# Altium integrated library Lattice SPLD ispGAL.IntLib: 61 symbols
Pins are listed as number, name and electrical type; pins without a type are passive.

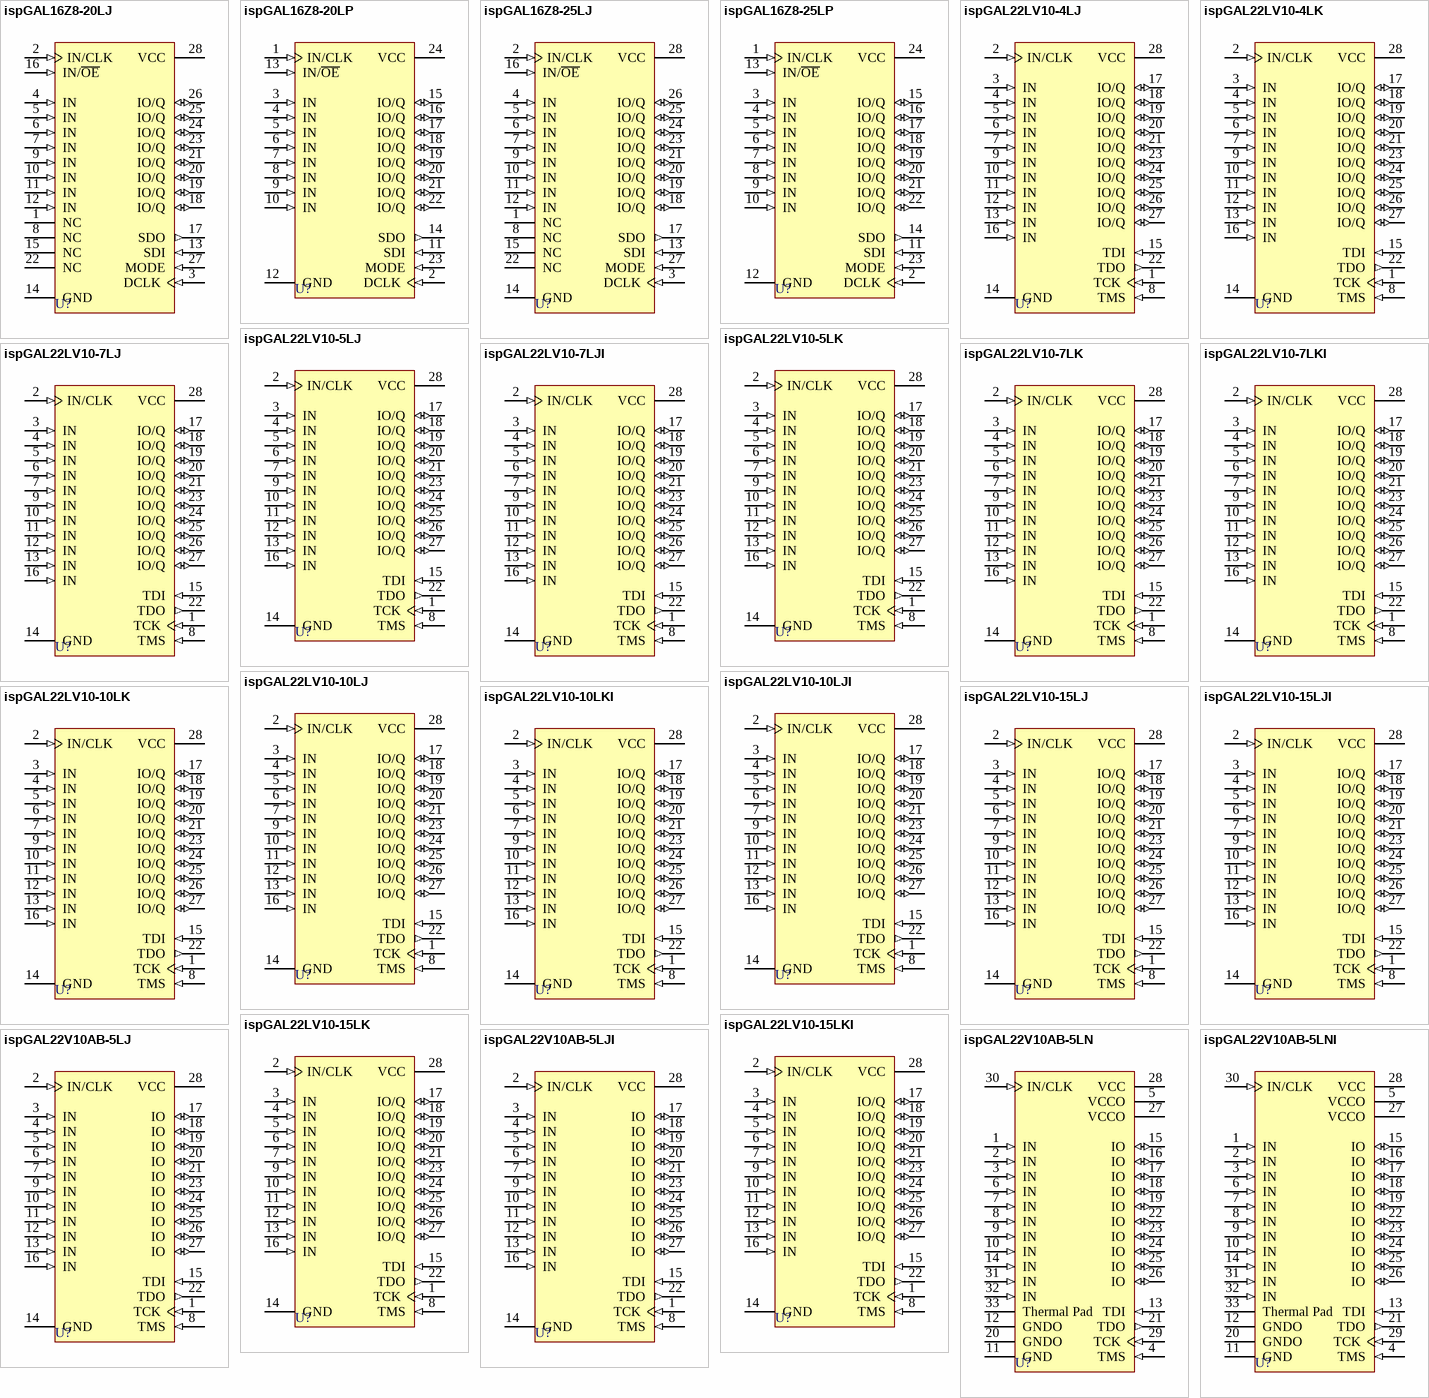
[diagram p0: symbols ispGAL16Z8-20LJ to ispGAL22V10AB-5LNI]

## ispGAL16Z8-20LJ
designator U?
ispGAL16Z8 E²CMOS PLD Generic Array Logic: Low Power, 5.0 V, 20 ns, Commercial Grade; Note: Pins 1, 8, 15 and 22 are No internal Connection (NC) pins.
footprint PLCC28_N (Leaded Chip Carrier, 28-Leads, Body 11.5x11.5mm, Pitch 1.27mm, IPC Medium Density)
footprint PLCC28_L (Leaded Chip Carrier, 28-Leads, Body 11.5x11.5mm, Pitch 1.27mm, IPC High Density)
footprint PLCC28_M (Leaded Chip Carrier, 28-Leads, Body 11.5x11.5mm, Pitch 1.27mm, IPC Low Density)
3D model 16Z8-PLCC28 (28-Pin Leaded Chip Carrier 1.27 mm Pitch)
pins: 1 NC, 2 IN/CLK (in), 3 DCLK (in), 4 IN (in), 5 IN (in), 6 IN (in), 7 IN (in), 8 NC, 9 IN (in), 10 IN (in), 11 IN (in), 12 IN (in), 13 SDI (in), 14 GND (power), 15 NC, 16 IN/~{OE} (in), 17 SDO (out), 18 IO/Q (io), 19 IO/Q (io), 20 IO/Q (io), 21 IO/Q (io), 22 NC, 23 IO/Q (io), 24 IO/Q (io), 25 IO/Q (io), 26 IO/Q (io), 27 MODE (in), 28 VCC (power)

## ispGAL16Z8-20LP
designator U?
ispGAL16Z8 E²CMOS PLD Generic Array Logic: Low Power, 5.0 V, 20 ns, Commercial Grade
footprint PDIP24 (DIP; 24 Leads; Row Spacing 7.62 mm; Pitch 2.54 mm)
3D model DIP24 (DIP; 24 Leads; Row Spacing 7.62 mm; Pitch 2.54 mm)
pins: 1 IN/CLK (in), 2 DCLK (in), 3 IN (in), 4 IN (in), 5 IN (in), 6 IN (in), 7 IN (in), 8 IN (in), 9 IN (in), 10 IN (in), 11 SDI (in), 12 GND (power), 13 IN/~{OE} (in), 14 SDO (out), 15 IO/Q (io), 16 IO/Q (io), 17 IO/Q (io), 18 IO/Q (io), 19 IO/Q (io), 20 IO/Q (io), 21 IO/Q (io), 22 IO/Q (io), 23 MODE (in), 24 VCC (power)

## ispGAL16Z8-25LJ
designator U?
ispGAL16Z8 E²CMOS PLD Generic Array Logic: Low Power, 5.0 V, 25 ns, Commercial Grade; Note: Pins 1, 8, 15 and 22 are No internal Connection (NC) pins.
footprint PLCC28_N (Leaded Chip Carrier, 28-Leads, Body 11.5x11.5mm, Pitch 1.27mm, IPC Medium Density)
footprint PLCC28_L (Leaded Chip Carrier, 28-Leads, Body 11.5x11.5mm, Pitch 1.27mm, IPC High Density)
footprint PLCC28_M (Leaded Chip Carrier, 28-Leads, Body 11.5x11.5mm, Pitch 1.27mm, IPC Low Density)
3D model 16Z8-PLCC28 (28-Pin Leaded Chip Carrier 1.27 mm Pitch)
pins: 1 NC, 2 IN/CLK (in), 3 DCLK (in), 4 IN (in), 5 IN (in), 6 IN (in), 7 IN (in), 8 NC, 9 IN (in), 10 IN (in), 11 IN (in), 12 IN (in), 13 SDI (in), 14 GND (power), 15 NC, 16 IN/~{OE} (in), 17 SDO (out), 18 IO/Q (io), 19 IO/Q (io), 20 IO/Q (io), 21 IO/Q (io), 22 NC, 23 IO/Q (io), 24 IO/Q (io), 25 IO/Q (io), 26 IO/Q (io), 27 MODE (in), 28 VCC (power)

## ispGAL16Z8-25LP
designator U?
ispGAL16Z8 E²CMOS PLD Generic Array Logic: Low Power, 5.0 V, 25 ns, Commercial Grade
footprint PDIP24 (DIP; 24 Leads; Row Spacing 7.62 mm; Pitch 2.54 mm)
3D model DIP24 (DIP; 24 Leads; Row Spacing 7.62 mm; Pitch 2.54 mm)
pins: 1 IN/CLK (in), 2 DCLK (in), 3 IN (in), 4 IN (in), 5 IN (in), 6 IN (in), 7 IN (in), 8 IN (in), 9 IN (in), 10 IN (in), 11 SDI (in), 12 GND (power), 13 IN/~{OE} (in), 14 SDO (out), 15 IO/Q (io), 16 IO/Q (io), 17 IO/Q (io), 18 IO/Q (io), 19 IO/Q (io), 20 IO/Q (io), 21 IO/Q (io), 22 IO/Q (io), 23 MODE (in), 24 VCC (power)

## ispGAL22LV10-4LJ
designator U?
ispGAL22LV10 E²CMOS PLD Generic Array Logic: Low Power, 3.3 V, 4.0 ns, Commercial Grade
footprint PLCC28_N (Leaded Chip Carrier, 28-Leads, Body 11.5x11.5mm, Pitch 1.27mm, IPC Medium Density)
footprint PLCC28_L (Leaded Chip Carrier, 28-Leads, Body 11.5x11.5mm, Pitch 1.27mm, IPC High Density)
footprint PLCC28_M (Leaded Chip Carrier, 28-Leads, Body 11.5x11.5mm, Pitch 1.27mm, IPC Low Density)
3D model 22LV10-PLCC28 (28-Pin Leaded Chip Carrier 1.27 mm Pitch)
pins: 1 TCK (in), 2 IN/CLK (in), 3 IN (in), 4 IN (in), 5 IN (in), 6 IN (in), 7 IN (in), 8 TMS (in), 9 IN (in), 10 IN (in), 11 IN (in), 12 IN (in), 13 IN (in), 14 GND (power), 15 TDI (in), 16 IN (in), 17 IO/Q (io), 18 IO/Q (io), 19 IO/Q (io), 20 IO/Q (io), 21 IO/Q (io), 22 TDO (out), 23 IO/Q (io), 24 IO/Q (io), 25 IO/Q (io), 26 IO/Q (io), 27 IO/Q (io), 28 VCC (power)

## ispGAL22LV10-4LK
designator U?
ispGAL22LV10 E²CMOS PLD Generic Array Logic: Low Power, 3.3 V, 4.0 ns, Commercial Grade
footprint SSOP28 (SSOP; 28 Leads; Body Width 5.3 mm; Pitch 0.65 mm)
3D model SSOP28 (SSOP; 28 Leads; Body Width 5.3 mm; Pitch 0.65 mm)
pins: 1 TCK (in), 2 IN/CLK (in), 3 IN (in), 4 IN (in), 5 IN (in), 6 IN (in), 7 IN (in), 8 TMS (in), 9 IN (in), 10 IN (in), 11 IN (in), 12 IN (in), 13 IN (in), 14 GND (power), 15 TDI (in), 16 IN (in), 17 IO/Q (io), 18 IO/Q (io), 19 IO/Q (io), 20 IO/Q (io), 21 IO/Q (io), 22 TDO (out), 23 IO/Q (io), 24 IO/Q (io), 25 IO/Q (io), 26 IO/Q (io), 27 IO/Q (io), 28 VCC (power)

## ispGAL22LV10-5LJ
designator U?
ispGAL22LV10 E²CMOS PLD Generic Array Logic: Low Power, 3.3 V, 5.0 ns, Commercial Grade
footprint PLCC28_N (Leaded Chip Carrier, 28-Leads, Body 11.5x11.5mm, Pitch 1.27mm, IPC Medium Density)
footprint PLCC28_L (Leaded Chip Carrier, 28-Leads, Body 11.5x11.5mm, Pitch 1.27mm, IPC High Density)
footprint PLCC28_M (Leaded Chip Carrier, 28-Leads, Body 11.5x11.5mm, Pitch 1.27mm, IPC Low Density)
3D model 22LV10-PLCC28 (28-Pin Leaded Chip Carrier 1.27 mm Pitch)
pins: 1 TCK (in), 2 IN/CLK (in), 3 IN (in), 4 IN (in), 5 IN (in), 6 IN (in), 7 IN (in), 8 TMS (in), 9 IN (in), 10 IN (in), 11 IN (in), 12 IN (in), 13 IN (in), 14 GND (power), 15 TDI (in), 16 IN (in), 17 IO/Q (io), 18 IO/Q (io), 19 IO/Q (io), 20 IO/Q (io), 21 IO/Q (io), 22 TDO (out), 23 IO/Q (io), 24 IO/Q (io), 25 IO/Q (io), 26 IO/Q (io), 27 IO/Q (io), 28 VCC (power)

## ispGAL22LV10-5LK
designator U?
ispGAL22LV10 E²CMOS PLD Generic Array Logic: Low Power, 3.3 V, 5.0 ns, Commercial Grade
footprint SSOP28 (SSOP; 28 Leads; Body Width 5.3 mm; Pitch 0.65 mm)
3D model SSOP28 (SSOP; 28 Leads; Body Width 5.3 mm; Pitch 0.65 mm)
pins: 1 TCK (in), 2 IN/CLK (in), 3 IN (in), 4 IN (in), 5 IN (in), 6 IN (in), 7 IN (in), 8 TMS (in), 9 IN (in), 10 IN (in), 11 IN (in), 12 IN (in), 13 IN (in), 14 GND (power), 15 TDI (in), 16 IN (in), 17 IO/Q (io), 18 IO/Q (io), 19 IO/Q (io), 20 IO/Q (io), 21 IO/Q (io), 22 TDO (out), 23 IO/Q (io), 24 IO/Q (io), 25 IO/Q (io), 26 IO/Q (io), 27 IO/Q (io), 28 VCC (power)

## ispGAL22LV10-7LJ
designator U?
ispGAL22LV10 E²CMOS PLD Generic Array Logic: Low Power, 3.3 V, 7.5 ns, Commercial Grade
footprint PLCC28_N (Leaded Chip Carrier, 28-Leads, Body 11.5x11.5mm, Pitch 1.27mm, IPC Medium Density)
footprint PLCC28_L (Leaded Chip Carrier, 28-Leads, Body 11.5x11.5mm, Pitch 1.27mm, IPC High Density)
footprint PLCC28_M (Leaded Chip Carrier, 28-Leads, Body 11.5x11.5mm, Pitch 1.27mm, IPC Low Density)
3D model 22LV10-PLCC28 (28-Pin Leaded Chip Carrier 1.27 mm Pitch)
pins: 1 TCK (in), 2 IN/CLK (in), 3 IN (in), 4 IN (in), 5 IN (in), 6 IN (in), 7 IN (in), 8 TMS (in), 9 IN (in), 10 IN (in), 11 IN (in), 12 IN (in), 13 IN (in), 14 GND (power), 15 TDI (in), 16 IN (in), 17 IO/Q (io), 18 IO/Q (io), 19 IO/Q (io), 20 IO/Q (io), 21 IO/Q (io), 22 TDO (out), 23 IO/Q (io), 24 IO/Q (io), 25 IO/Q (io), 26 IO/Q (io), 27 IO/Q (io), 28 VCC (power)

## ispGAL22LV10-7LJI
designator U?
ispGAL22LV10 E²CMOS PLD Generic Array Logic: Low Power, 3.3 V, 7.5 ns, Industrial Grade
footprint PLCC28_N (Leaded Chip Carrier, 28-Leads, Body 11.5x11.5mm, Pitch 1.27mm, IPC Medium Density)
footprint PLCC28_L (Leaded Chip Carrier, 28-Leads, Body 11.5x11.5mm, Pitch 1.27mm, IPC High Density)
footprint PLCC28_M (Leaded Chip Carrier, 28-Leads, Body 11.5x11.5mm, Pitch 1.27mm, IPC Low Density)
3D model 22LV10-PLCC28 (28-Pin Leaded Chip Carrier 1.27 mm Pitch)
pins: 1 TCK (in), 2 IN/CLK (in), 3 IN (in), 4 IN (in), 5 IN (in), 6 IN (in), 7 IN (in), 8 TMS (in), 9 IN (in), 10 IN (in), 11 IN (in), 12 IN (in), 13 IN (in), 14 GND (power), 15 TDI (in), 16 IN (in), 17 IO/Q (io), 18 IO/Q (io), 19 IO/Q (io), 20 IO/Q (io), 21 IO/Q (io), 22 TDO (out), 23 IO/Q (io), 24 IO/Q (io), 25 IO/Q (io), 26 IO/Q (io), 27 IO/Q (io), 28 VCC (power)

## ispGAL22LV10-7LK
designator U?
ispGAL22LV10 E²CMOS PLD Generic Array Logic: Low Power, 3.3 V, 7.5 ns, Commercial Grade
footprint SSOP28 (SSOP; 28 Leads; Body Width 5.3 mm; Pitch 0.65 mm)
3D model SSOP28 (SSOP; 28 Leads; Body Width 5.3 mm; Pitch 0.65 mm)
pins: 1 TCK (in), 2 IN/CLK (in), 3 IN (in), 4 IN (in), 5 IN (in), 6 IN (in), 7 IN (in), 8 TMS (in), 9 IN (in), 10 IN (in), 11 IN (in), 12 IN (in), 13 IN (in), 14 GND (power), 15 TDI (in), 16 IN (in), 17 IO/Q (io), 18 IO/Q (io), 19 IO/Q (io), 20 IO/Q (io), 21 IO/Q (io), 22 TDO (out), 23 IO/Q (io), 24 IO/Q (io), 25 IO/Q (io), 26 IO/Q (io), 27 IO/Q (io), 28 VCC (power)

## ispGAL22LV10-7LKI
designator U?
ispGAL22LV10 E²CMOS PLD Generic Array Logic: Low Power, 3.3 V, 7.5 ns, Industrial Grade
footprint SSOP28 (SSOP; 28 Leads; Body Width 5.3 mm; Pitch 0.65 mm)
3D model SSOP28 (SSOP; 28 Leads; Body Width 5.3 mm; Pitch 0.65 mm)
pins: 1 TCK (in), 2 IN/CLK (in), 3 IN (in), 4 IN (in), 5 IN (in), 6 IN (in), 7 IN (in), 8 TMS (in), 9 IN (in), 10 IN (in), 11 IN (in), 12 IN (in), 13 IN (in), 14 GND (power), 15 TDI (in), 16 IN (in), 17 IO/Q (io), 18 IO/Q (io), 19 IO/Q (io), 20 IO/Q (io), 21 IO/Q (io), 22 TDO (out), 23 IO/Q (io), 24 IO/Q (io), 25 IO/Q (io), 26 IO/Q (io), 27 IO/Q (io), 28 VCC (power)

## ispGAL22LV10-10LJ
designator U?
ispGAL22LV10 E²CMOS PLD Generic Array Logic: Low Power, 3.3 V, 10 ns, Commercial Grade
footprint PLCC28_N (Leaded Chip Carrier, 28-Leads, Body 11.5x11.5mm, Pitch 1.27mm, IPC Medium Density)
footprint PLCC28_L (Leaded Chip Carrier, 28-Leads, Body 11.5x11.5mm, Pitch 1.27mm, IPC High Density)
footprint PLCC28_M (Leaded Chip Carrier, 28-Leads, Body 11.5x11.5mm, Pitch 1.27mm, IPC Low Density)
3D model 22LV10-PLCC28 (28-Pin Leaded Chip Carrier 1.27 mm Pitch)
pins: 1 TCK (in), 2 IN/CLK (in), 3 IN (in), 4 IN (in), 5 IN (in), 6 IN (in), 7 IN (in), 8 TMS (in), 9 IN (in), 10 IN (in), 11 IN (in), 12 IN (in), 13 IN (in), 14 GND (power), 15 TDI (in), 16 IN (in), 17 IO/Q (io), 18 IO/Q (io), 19 IO/Q (io), 20 IO/Q (io), 21 IO/Q (io), 22 TDO (out), 23 IO/Q (io), 24 IO/Q (io), 25 IO/Q (io), 26 IO/Q (io), 27 IO/Q (io), 28 VCC (power)

## ispGAL22LV10-10LJI
designator U?
ispGAL22LV10 E²CMOS PLD Generic Array Logic: Low Power, 3.3 V, 10 ns, Industrial Grade
footprint PLCC28_N (Leaded Chip Carrier, 28-Leads, Body 11.5x11.5mm, Pitch 1.27mm, IPC Medium Density)
footprint PLCC28_L (Leaded Chip Carrier, 28-Leads, Body 11.5x11.5mm, Pitch 1.27mm, IPC High Density)
footprint PLCC28_M (Leaded Chip Carrier, 28-Leads, Body 11.5x11.5mm, Pitch 1.27mm, IPC Low Density)
3D model 22LV10-PLCC28 (28-Pin Leaded Chip Carrier 1.27 mm Pitch)
pins: 1 TCK (in), 2 IN/CLK (in), 3 IN (in), 4 IN (in), 5 IN (in), 6 IN (in), 7 IN (in), 8 TMS (in), 9 IN (in), 10 IN (in), 11 IN (in), 12 IN (in), 13 IN (in), 14 GND (power), 15 TDI (in), 16 IN (in), 17 IO/Q (io), 18 IO/Q (io), 19 IO/Q (io), 20 IO/Q (io), 21 IO/Q (io), 22 TDO (out), 23 IO/Q (io), 24 IO/Q (io), 25 IO/Q (io), 26 IO/Q (io), 27 IO/Q (io), 28 VCC (power)

## ispGAL22LV10-10LK
designator U?
ispGAL22LV10 E²CMOS PLD Generic Array Logic: Low Power, 3.3 V, 10 ns, Commercial Grade
footprint SSOP28 (SSOP; 28 Leads; Body Width 5.3 mm; Pitch 0.65 mm)
3D model SSOP28 (SSOP; 28 Leads; Body Width 5.3 mm; Pitch 0.65 mm)
pins: 1 TCK (in), 2 IN/CLK (in), 3 IN (in), 4 IN (in), 5 IN (in), 6 IN (in), 7 IN (in), 8 TMS (in), 9 IN (in), 10 IN (in), 11 IN (in), 12 IN (in), 13 IN (in), 14 GND (power), 15 TDI (in), 16 IN (in), 17 IO/Q (io), 18 IO/Q (io), 19 IO/Q (io), 20 IO/Q (io), 21 IO/Q (io), 22 TDO (out), 23 IO/Q (io), 24 IO/Q (io), 25 IO/Q (io), 26 IO/Q (io), 27 IO/Q (io), 28 VCC (power)

## ispGAL22LV10-10LKI
designator U?
ispGAL22LV10 E²CMOS PLD Generic Array Logic: Low Power, 3.3 V, 10 ns, Industrial Grade
footprint SSOP28 (SSOP; 28 Leads; Body Width 5.3 mm; Pitch 0.65 mm)
3D model SSOP28 (SSOP; 28 Leads; Body Width 5.3 mm; Pitch 0.65 mm)
pins: 1 TCK (in), 2 IN/CLK (in), 3 IN (in), 4 IN (in), 5 IN (in), 6 IN (in), 7 IN (in), 8 TMS (in), 9 IN (in), 10 IN (in), 11 IN (in), 12 IN (in), 13 IN (in), 14 GND (power), 15 TDI (in), 16 IN (in), 17 IO/Q (io), 18 IO/Q (io), 19 IO/Q (io), 20 IO/Q (io), 21 IO/Q (io), 22 TDO (out), 23 IO/Q (io), 24 IO/Q (io), 25 IO/Q (io), 26 IO/Q (io), 27 IO/Q (io), 28 VCC (power)

## ispGAL22LV10-15LJ
designator U?
ispGAL22LV10 E²CMOS PLD Generic Array Logic: Low Power, 3.3 V, 15 ns, Commercial Grade
footprint PLCC28_N (Leaded Chip Carrier, 28-Leads, Body 11.5x11.5mm, Pitch 1.27mm, IPC Medium Density)
footprint PLCC28_L (Leaded Chip Carrier, 28-Leads, Body 11.5x11.5mm, Pitch 1.27mm, IPC High Density)
footprint PLCC28_M (Leaded Chip Carrier, 28-Leads, Body 11.5x11.5mm, Pitch 1.27mm, IPC Low Density)
3D model 22LV10-PLCC28 (28-Pin Leaded Chip Carrier 1.27 mm Pitch)
pins: 1 TCK (in), 2 IN/CLK (in), 3 IN (in), 4 IN (in), 5 IN (in), 6 IN (in), 7 IN (in), 8 TMS (in), 9 IN (in), 10 IN (in), 11 IN (in), 12 IN (in), 13 IN (in), 14 GND (power), 15 TDI (in), 16 IN (in), 17 IO/Q (io), 18 IO/Q (io), 19 IO/Q (io), 20 IO/Q (io), 21 IO/Q (io), 22 TDO (out), 23 IO/Q (io), 24 IO/Q (io), 25 IO/Q (io), 26 IO/Q (io), 27 IO/Q (io), 28 VCC (power)

## ispGAL22LV10-15LJI
designator U?
ispGAL22LV10 E²CMOS PLD Generic Array Logic: Low Power, 3.3 V, 15 ns, Industrial Grade
footprint PLCC28_N (Leaded Chip Carrier, 28-Leads, Body 11.5x11.5mm, Pitch 1.27mm, IPC Medium Density)
footprint PLCC28_L (Leaded Chip Carrier, 28-Leads, Body 11.5x11.5mm, Pitch 1.27mm, IPC High Density)
footprint PLCC28_M (Leaded Chip Carrier, 28-Leads, Body 11.5x11.5mm, Pitch 1.27mm, IPC Low Density)
3D model 22LV10-PLCC28 (28-Pin Leaded Chip Carrier 1.27 mm Pitch)
pins: 1 TCK (in), 2 IN/CLK (in), 3 IN (in), 4 IN (in), 5 IN (in), 6 IN (in), 7 IN (in), 8 TMS (in), 9 IN (in), 10 IN (in), 11 IN (in), 12 IN (in), 13 IN (in), 14 GND (power), 15 TDI (in), 16 IN (in), 17 IO/Q (io), 18 IO/Q (io), 19 IO/Q (io), 20 IO/Q (io), 21 IO/Q (io), 22 TDO (out), 23 IO/Q (io), 24 IO/Q (io), 25 IO/Q (io), 26 IO/Q (io), 27 IO/Q (io), 28 VCC (power)

## ispGAL22LV10-15LK
designator U?
ispGAL22LV10 E²CMOS PLD Generic Array Logic: Low Power, 3.3 V, 15 ns, Commercial Grade
footprint SSOP28 (SSOP; 28 Leads; Body Width 5.3 mm; Pitch 0.65 mm)
3D model SSOP28 (SSOP; 28 Leads; Body Width 5.3 mm; Pitch 0.65 mm)
pins: 1 TCK (in), 2 IN/CLK (in), 3 IN (in), 4 IN (in), 5 IN (in), 6 IN (in), 7 IN (in), 8 TMS (in), 9 IN (in), 10 IN (in), 11 IN (in), 12 IN (in), 13 IN (in), 14 GND (power), 15 TDI (in), 16 IN (in), 17 IO/Q (io), 18 IO/Q (io), 19 IO/Q (io), 20 IO/Q (io), 21 IO/Q (io), 22 TDO (out), 23 IO/Q (io), 24 IO/Q (io), 25 IO/Q (io), 26 IO/Q (io), 27 IO/Q (io), 28 VCC (power)

## ispGAL22LV10-15LKI
designator U?
ispGAL22LV10 E²CMOS PLD Generic Array Logic: Low Power, 3.3 V, 15 ns, Industrial Grade
footprint SSOP28 (SSOP; 28 Leads; Body Width 5.3 mm; Pitch 0.65 mm)
3D model SSOP28 (SSOP; 28 Leads; Body Width 5.3 mm; Pitch 0.65 mm)
pins: 1 TCK (in), 2 IN/CLK (in), 3 IN (in), 4 IN (in), 5 IN (in), 6 IN (in), 7 IN (in), 8 TMS (in), 9 IN (in), 10 IN (in), 11 IN (in), 12 IN (in), 13 IN (in), 14 GND (power), 15 TDI (in), 16 IN (in), 17 IO/Q (io), 18 IO/Q (io), 19 IO/Q (io), 20 IO/Q (io), 21 IO/Q (io), 22 TDO (out), 23 IO/Q (io), 24 IO/Q (io), 25 IO/Q (io), 26 IO/Q (io), 27 IO/Q (io), 28 VCC (power)

## ispGAL22V10AB-5LJ
designator U?
ispGAL22V10AB E²CMOS PLD Generic Array Logic: Low Power, 2.5 V, 5.0 ns, Commercial Grade
footprint PLCC28_N (Leaded Chip Carrier, 28-Leads, Body 11.5x11.5mm, Pitch 1.27mm, IPC Medium Density)
footprint PLCC28_L (Leaded Chip Carrier, 28-Leads, Body 11.5x11.5mm, Pitch 1.27mm, IPC High Density)
footprint PLCC28_M (Leaded Chip Carrier, 28-Leads, Body 11.5x11.5mm, Pitch 1.27mm, IPC Low Density)
3D model 22V10AB-PLCC28 (28-Pin Leaded Chip Carrier 1.27 mm Pitch)
pins: 1 TCK (in), 2 IN/CLK (in), 3 IN (in), 4 IN (in), 5 IN (in), 6 IN (in), 7 IN (in), 8 TMS (in), 9 IN (in), 10 IN (in), 11 IN (in), 12 IN (in), 13 IN (in), 14 GND (power), 15 TDI (in), 16 IN (in), 17 IO (io), 18 IO (io), 19 IO (io), 20 IO (io), 21 IO (io), 22 TDO (out), 23 IO (io), 24 IO (io), 25 IO (io), 26 IO (io), 27 IO (io), 28 VCC (power)

## ispGAL22V10AB-5LJI
designator U?
ispGAL22V10AB E²CMOS PLD Generic Array Logic: Low Power, 2.5 V, 5.0 ns, Industrial Grade
footprint PLCC28_N (Leaded Chip Carrier, 28-Leads, Body 11.5x11.5mm, Pitch 1.27mm, IPC Medium Density)
footprint PLCC28_L (Leaded Chip Carrier, 28-Leads, Body 11.5x11.5mm, Pitch 1.27mm, IPC High Density)
footprint PLCC28_M (Leaded Chip Carrier, 28-Leads, Body 11.5x11.5mm, Pitch 1.27mm, IPC Low Density)
3D model 22V10AB-PLCC28 (28-Pin Leaded Chip Carrier 1.27 mm Pitch)
pins: 1 TCK (in), 2 IN/CLK (in), 3 IN (in), 4 IN (in), 5 IN (in), 6 IN (in), 7 IN (in), 8 TMS (in), 9 IN (in), 10 IN (in), 11 IN (in), 12 IN (in), 13 IN (in), 14 GND (power), 15 TDI (in), 16 IN (in), 17 IO (io), 18 IO (io), 19 IO (io), 20 IO (io), 21 IO (io), 22 TDO (out), 23 IO (io), 24 IO (io), 25 IO (io), 26 IO (io), 27 IO (io), 28 VCC (power)

## ispGAL22V10AB-5LN
designator U?
ispGAL22V10AB E²CMOS PLD Generic Array Logic: Low Power, 2.5 V, 5.0 ns, Commercial Grade
footprint QFN32_N (QFN, 32-Leads, Body 5x5mm, Pitch 0.5mm, IPC Medium Density)
footprint QFN32_L (QFN, 32-Leads, Body 5x5mm, Pitch 0.5mm, IPC High Density)
footprint QFN32_M (QFN, 32-Leads, Body 5x5mm, Pitch 0.5mm, IPC Low Density)
pins: 1 IN (in), 2 IN (in), 3 IN (in), 4 TMS (in), 5 VCCO (power), 6 IN (in), 7 IN (in), 8 IN (in), 9 IN (in), 10 IN (in), 11 GND (power), 12 GNDO (power), 13 TDI (in), 14 IN (in), 15 IO (io), 16 IO (io), 17 IO (io), 18 IO (io), 19 IO (io), 20 GNDO (power), 21 TDO (out), 22 IO (io), 23 IO (io), 24 IO (io), 25 IO (io), 26 IO (io), 27 VCCO (power), 28 VCC (power), 29 TCK (in), 30 IN/CLK (in), 31 IN (in), 32 IN (in), 33 Thermal Pad (power)

## ispGAL22V10AB-5LNI
designator U?
ispGAL22V10AB E²CMOS PLD Generic Array Logic: Low Power, 2.5 V, 5.0 ns, Industrial Grade
footprint QFN32_N (QFN, 32-Leads, Body 5x5mm, Pitch 0.5mm, IPC Medium Density)
footprint QFN32_L (QFN, 32-Leads, Body 5x5mm, Pitch 0.5mm, IPC High Density)
footprint QFN32_M (QFN, 32-Leads, Body 5x5mm, Pitch 0.5mm, IPC Low Density)
pins: 1 IN (in), 2 IN (in), 3 IN (in), 4 TMS (in), 5 VCCO (power), 6 IN (in), 7 IN (in), 8 IN (in), 9 IN (in), 10 IN (in), 11 GND (power), 12 GNDO (power), 13 TDI (in), 14 IN (in), 15 IO (io), 16 IO (io), 17 IO (io), 18 IO (io), 19 IO (io), 20 GNDO (power), 21 TDO (out), 22 IO (io), 23 IO (io), 24 IO (io), 25 IO (io), 26 IO (io), 27 VCCO (power), 28 VCC (power), 29 TCK (in), 30 IN/CLK (in), 31 IN (in), 32 IN (in), 33 Thermal Pad (power)

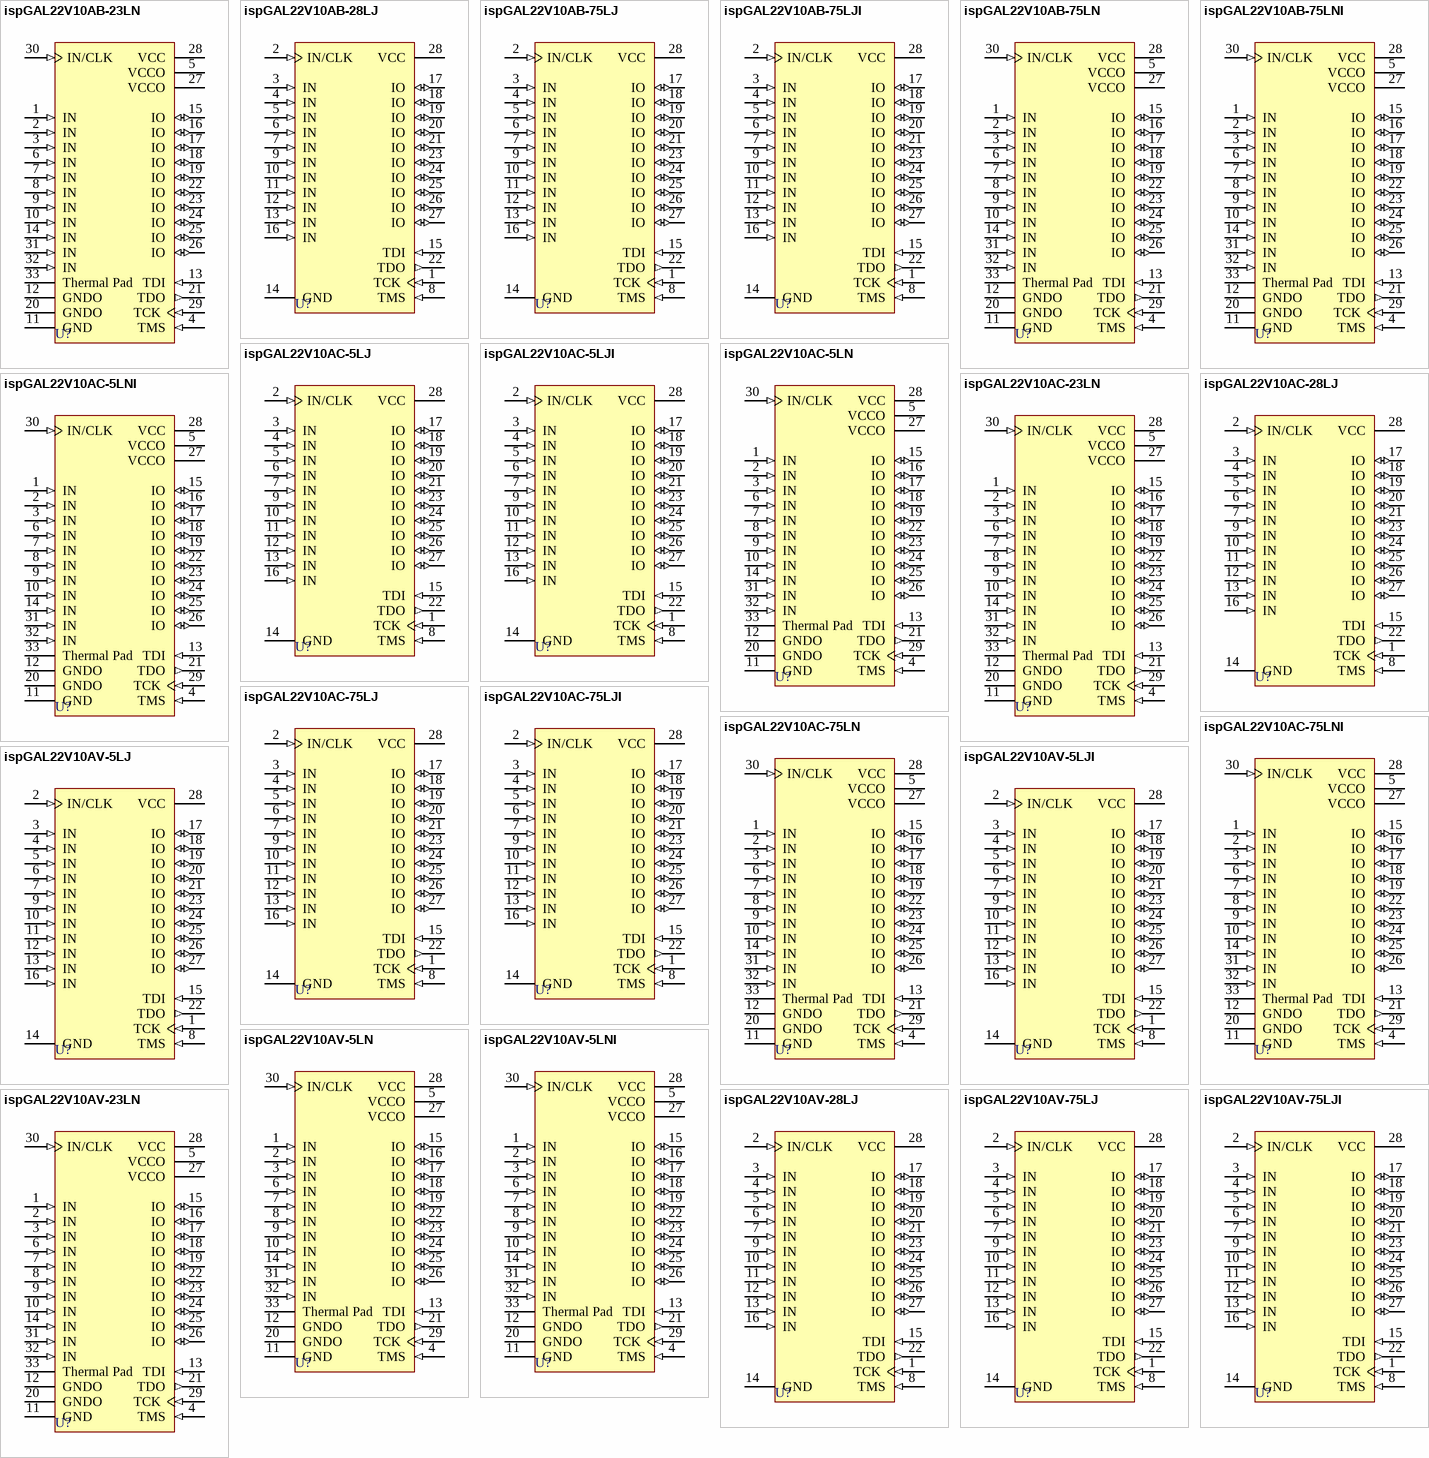
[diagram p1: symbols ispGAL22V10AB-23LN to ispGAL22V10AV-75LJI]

## ispGAL22V10AB-23LN
designator U?
ispGAL22V10AB E²CMOS PLD Generic Array Logic: Low Power, 2.5 V, 2.3 ns, Commercial Grade
footprint QFN32_N (QFN, 32-Leads, Body 5x5mm, Pitch 0.5mm, IPC Medium Density)
footprint QFN32_L (QFN, 32-Leads, Body 5x5mm, Pitch 0.5mm, IPC High Density)
footprint QFN32_M (QFN, 32-Leads, Body 5x5mm, Pitch 0.5mm, IPC Low Density)
pins: 1 IN (in), 2 IN (in), 3 IN (in), 4 TMS (in), 5 VCCO (power), 6 IN (in), 7 IN (in), 8 IN (in), 9 IN (in), 10 IN (in), 11 GND (power), 12 GNDO (power), 13 TDI (in), 14 IN (in), 15 IO (io), 16 IO (io), 17 IO (io), 18 IO (io), 19 IO (io), 20 GNDO (power), 21 TDO (out), 22 IO (io), 23 IO (io), 24 IO (io), 25 IO (io), 26 IO (io), 27 VCCO (power), 28 VCC (power), 29 TCK (in), 30 IN/CLK (in), 31 IN (in), 32 IN (in), 33 Thermal Pad (power)

## ispGAL22V10AB-28LJ
designator U?
ispGAL22V10AB E²CMOS PLD Generic Array Logic: Low Power, 2.5 V, 2.8 ns, Commercial Grade
footprint PLCC28_N (Leaded Chip Carrier, 28-Leads, Body 11.5x11.5mm, Pitch 1.27mm, IPC Medium Density)
footprint PLCC28_L (Leaded Chip Carrier, 28-Leads, Body 11.5x11.5mm, Pitch 1.27mm, IPC High Density)
footprint PLCC28_M (Leaded Chip Carrier, 28-Leads, Body 11.5x11.5mm, Pitch 1.27mm, IPC Low Density)
3D model 22V10AB-PLCC28 (28-Pin Leaded Chip Carrier 1.27 mm Pitch)
pins: 1 TCK (in), 2 IN/CLK (in), 3 IN (in), 4 IN (in), 5 IN (in), 6 IN (in), 7 IN (in), 8 TMS (in), 9 IN (in), 10 IN (in), 11 IN (in), 12 IN (in), 13 IN (in), 14 GND (power), 15 TDI (in), 16 IN (in), 17 IO (io), 18 IO (io), 19 IO (io), 20 IO (io), 21 IO (io), 22 TDO (out), 23 IO (io), 24 IO (io), 25 IO (io), 26 IO (io), 27 IO (io), 28 VCC (power)

## ispGAL22V10AB-75LJ
designator U?
ispGAL22V10AB E²CMOS PLD Generic Array Logic: Low Power, 2.5 V, 7.5 ns, Commercial Grade
footprint PLCC28_N (Leaded Chip Carrier, 28-Leads, Body 11.5x11.5mm, Pitch 1.27mm, IPC Medium Density)
footprint PLCC28_L (Leaded Chip Carrier, 28-Leads, Body 11.5x11.5mm, Pitch 1.27mm, IPC High Density)
footprint PLCC28_M (Leaded Chip Carrier, 28-Leads, Body 11.5x11.5mm, Pitch 1.27mm, IPC Low Density)
3D model 22V10AB-PLCC28 (28-Pin Leaded Chip Carrier 1.27 mm Pitch)
pins: 1 TCK (in), 2 IN/CLK (in), 3 IN (in), 4 IN (in), 5 IN (in), 6 IN (in), 7 IN (in), 8 TMS (in), 9 IN (in), 10 IN (in), 11 IN (in), 12 IN (in), 13 IN (in), 14 GND (power), 15 TDI (in), 16 IN (in), 17 IO (io), 18 IO (io), 19 IO (io), 20 IO (io), 21 IO (io), 22 TDO (out), 23 IO (io), 24 IO (io), 25 IO (io), 26 IO (io), 27 IO (io), 28 VCC (power)

## ispGAL22V10AB-75LJI
designator U?
ispGAL22V10AB E²CMOS PLD Generic Array Logic: Low Power, 2.5 V, 7.5 ns, Industrial Grade
footprint PLCC28_N (Leaded Chip Carrier, 28-Leads, Body 11.5x11.5mm, Pitch 1.27mm, IPC Medium Density)
footprint PLCC28_L (Leaded Chip Carrier, 28-Leads, Body 11.5x11.5mm, Pitch 1.27mm, IPC High Density)
footprint PLCC28_M (Leaded Chip Carrier, 28-Leads, Body 11.5x11.5mm, Pitch 1.27mm, IPC Low Density)
3D model 22V10AB-PLCC28 (28-Pin Leaded Chip Carrier 1.27 mm Pitch)
pins: 1 TCK (in), 2 IN/CLK (in), 3 IN (in), 4 IN (in), 5 IN (in), 6 IN (in), 7 IN (in), 8 TMS (in), 9 IN (in), 10 IN (in), 11 IN (in), 12 IN (in), 13 IN (in), 14 GND (power), 15 TDI (in), 16 IN (in), 17 IO (io), 18 IO (io), 19 IO (io), 20 IO (io), 21 IO (io), 22 TDO (out), 23 IO (io), 24 IO (io), 25 IO (io), 26 IO (io), 27 IO (io), 28 VCC (power)

## ispGAL22V10AB-75LN
designator U?
ispGAL22V10AB E²CMOS PLD Generic Array Logic: Low Power, 2.5 V, 7.5 ns, Commercial Grade
footprint QFN32_N (QFN, 32-Leads, Body 5x5mm, Pitch 0.5mm, IPC Medium Density)
footprint QFN32_L (QFN, 32-Leads, Body 5x5mm, Pitch 0.5mm, IPC High Density)
footprint QFN32_M (QFN, 32-Leads, Body 5x5mm, Pitch 0.5mm, IPC Low Density)
pins: 1 IN (in), 2 IN (in), 3 IN (in), 4 TMS (in), 5 VCCO (power), 6 IN (in), 7 IN (in), 8 IN (in), 9 IN (in), 10 IN (in), 11 GND (power), 12 GNDO (power), 13 TDI (in), 14 IN (in), 15 IO (io), 16 IO (io), 17 IO (io), 18 IO (io), 19 IO (io), 20 GNDO (power), 21 TDO (out), 22 IO (io), 23 IO (io), 24 IO (io), 25 IO (io), 26 IO (io), 27 VCCO (power), 28 VCC (power), 29 TCK (in), 30 IN/CLK (in), 31 IN (in), 32 IN (in), 33 Thermal Pad (power)

## ispGAL22V10AB-75LNI
designator U?
ispGAL22V10AB E²CMOS PLD Generic Array Logic: Low Power, 2.5 V, 7.5 ns, Industrial Grade
footprint QFN32_N (QFN, 32-Leads, Body 5x5mm, Pitch 0.5mm, IPC Medium Density)
footprint QFN32_L (QFN, 32-Leads, Body 5x5mm, Pitch 0.5mm, IPC High Density)
footprint QFN32_M (QFN, 32-Leads, Body 5x5mm, Pitch 0.5mm, IPC Low Density)
pins: 1 IN (in), 2 IN (in), 3 IN (in), 4 TMS (in), 5 VCCO (power), 6 IN (in), 7 IN (in), 8 IN (in), 9 IN (in), 10 IN (in), 11 GND (power), 12 GNDO (power), 13 TDI (in), 14 IN (in), 15 IO (io), 16 IO (io), 17 IO (io), 18 IO (io), 19 IO (io), 20 GNDO (power), 21 TDO (out), 22 IO (io), 23 IO (io), 24 IO (io), 25 IO (io), 26 IO (io), 27 VCCO (power), 28 VCC (power), 29 TCK (in), 30 IN/CLK (in), 31 IN (in), 32 IN (in), 33 Thermal Pad (power)

## ispGAL22V10AC-5LJ
designator U?
ispGAL22V10AC E²CMOS PLD Generic Array Logic: Low Power, 1.8 V, 5.0 ns, Commercial Grade
footprint PLCC28_N (Leaded Chip Carrier, 28-Leads, Body 11.5x11.5mm, Pitch 1.27mm, IPC Medium Density)
footprint PLCC28_L (Leaded Chip Carrier, 28-Leads, Body 11.5x11.5mm, Pitch 1.27mm, IPC High Density)
footprint PLCC28_M (Leaded Chip Carrier, 28-Leads, Body 11.5x11.5mm, Pitch 1.27mm, IPC Low Density)
3D model 22V10AC-PLCC28 (28-Pin Leaded Chip Carrier 1.27 mm Pitch)
pins: 1 TCK (in), 2 IN/CLK (in), 3 IN (in), 4 IN (in), 5 IN (in), 6 IN (in), 7 IN (in), 8 TMS (in), 9 IN (in), 10 IN (in), 11 IN (in), 12 IN (in), 13 IN (in), 14 GND (power), 15 TDI (in), 16 IN (in), 17 IO (io), 18 IO (io), 19 IO (io), 20 IO (io), 21 IO (io), 22 TDO (out), 23 IO (io), 24 IO (io), 25 IO (io), 26 IO (io), 27 IO (io), 28 VCC (power)

## ispGAL22V10AC-5LJI
designator U?
ispGAL22V10AC E²CMOS PLD Generic Array Logic: Low Power, 1.8 V, 5.0 ns, Industrial Grade
footprint PLCC28_N (Leaded Chip Carrier, 28-Leads, Body 11.5x11.5mm, Pitch 1.27mm, IPC Medium Density)
footprint PLCC28_L (Leaded Chip Carrier, 28-Leads, Body 11.5x11.5mm, Pitch 1.27mm, IPC High Density)
footprint PLCC28_M (Leaded Chip Carrier, 28-Leads, Body 11.5x11.5mm, Pitch 1.27mm, IPC Low Density)
3D model 22V10AC-PLCC28 (28-Pin Leaded Chip Carrier 1.27 mm Pitch)
pins: 1 TCK (in), 2 IN/CLK (in), 3 IN (in), 4 IN (in), 5 IN (in), 6 IN (in), 7 IN (in), 8 TMS (in), 9 IN (in), 10 IN (in), 11 IN (in), 12 IN (in), 13 IN (in), 14 GND (power), 15 TDI (in), 16 IN (in), 17 IO (io), 18 IO (io), 19 IO (io), 20 IO (io), 21 IO (io), 22 TDO (out), 23 IO (io), 24 IO (io), 25 IO (io), 26 IO (io), 27 IO (io), 28 VCC (power)

## ispGAL22V10AC-5LN
designator U?
ispGAL22V10AC E²CMOS PLD Generic Array Logic: Low Power, 1.8 V, 5.0 ns, Commercial Grade
footprint QFN32_N (QFN, 32-Leads, Body 5x5mm, Pitch 0.5mm, IPC Medium Density)
footprint QFN32_L (QFN, 32-Leads, Body 5x5mm, Pitch 0.5mm, IPC High Density)
footprint QFN32_M (QFN, 32-Leads, Body 5x5mm, Pitch 0.5mm, IPC Low Density)
pins: 1 IN (in), 2 IN (in), 3 IN (in), 4 TMS (in), 5 VCCO (power), 6 IN (in), 7 IN (in), 8 IN (in), 9 IN (in), 10 IN (in), 11 GND (power), 12 GNDO (power), 13 TDI (in), 14 IN (in), 15 IO (io), 16 IO (io), 17 IO (io), 18 IO (io), 19 IO (io), 20 GNDO (power), 21 TDO (out), 22 IO (io), 23 IO (io), 24 IO (io), 25 IO (io), 26 IO (io), 27 VCCO (power), 28 VCC (power), 29 TCK (in), 30 IN/CLK (in), 31 IN (in), 32 IN (in), 33 Thermal Pad (power)

## ispGAL22V10AC-5LNI
designator U?
ispGAL22V10AC E²CMOS PLD Generic Array Logic: Low Power, 1.8 V, 5.0 ns, Industrial Grade
footprint QFN32_N (QFN, 32-Leads, Body 5x5mm, Pitch 0.5mm, IPC Medium Density)
footprint QFN32_L (QFN, 32-Leads, Body 5x5mm, Pitch 0.5mm, IPC High Density)
footprint QFN32_M (QFN, 32-Leads, Body 5x5mm, Pitch 0.5mm, IPC Low Density)
pins: 1 IN (in), 2 IN (in), 3 IN (in), 4 TMS (in), 5 VCCO (power), 6 IN (in), 7 IN (in), 8 IN (in), 9 IN (in), 10 IN (in), 11 GND (power), 12 GNDO (power), 13 TDI (in), 14 IN (in), 15 IO (io), 16 IO (io), 17 IO (io), 18 IO (io), 19 IO (io), 20 GNDO (power), 21 TDO (out), 22 IO (io), 23 IO (io), 24 IO (io), 25 IO (io), 26 IO (io), 27 VCCO (power), 28 VCC (power), 29 TCK (in), 30 IN/CLK (in), 31 IN (in), 32 IN (in), 33 Thermal Pad (power)

## ispGAL22V10AC-23LN
designator U?
ispGAL22V10AC E²CMOS PLD Generic Array Logic: Low Power, 1.8 V, 2.3 ns, Commercial Grade
footprint QFN32_N (QFN, 32-Leads, Body 5x5mm, Pitch 0.5mm, IPC Medium Density)
footprint QFN32_L (QFN, 32-Leads, Body 5x5mm, Pitch 0.5mm, IPC High Density)
footprint QFN32_M (QFN, 32-Leads, Body 5x5mm, Pitch 0.5mm, IPC Low Density)
pins: 1 IN (in), 2 IN (in), 3 IN (in), 4 TMS (in), 5 VCCO (power), 6 IN (in), 7 IN (in), 8 IN (in), 9 IN (in), 10 IN (in), 11 GND (power), 12 GNDO (power), 13 TDI (in), 14 IN (in), 15 IO (io), 16 IO (io), 17 IO (io), 18 IO (io), 19 IO (io), 20 GNDO (power), 21 TDO (out), 22 IO (io), 23 IO (io), 24 IO (io), 25 IO (io), 26 IO (io), 27 VCCO (power), 28 VCC (power), 29 TCK (in), 30 IN/CLK (in), 31 IN (in), 32 IN (in), 33 Thermal Pad (power)

## ispGAL22V10AC-28LJ
designator U?
ispGAL22V10AC E²CMOS PLD Generic Array Logic: Low Power, 1.8 V, 2.8 ns, Commercial Grade
footprint PLCC28_N (Leaded Chip Carrier, 28-Leads, Body 11.5x11.5mm, Pitch 1.27mm, IPC Medium Density)
footprint PLCC28_L (Leaded Chip Carrier, 28-Leads, Body 11.5x11.5mm, Pitch 1.27mm, IPC High Density)
footprint PLCC28_M (Leaded Chip Carrier, 28-Leads, Body 11.5x11.5mm, Pitch 1.27mm, IPC Low Density)
3D model 22V10AC-PLCC28 (28-Pin Leaded Chip Carrier 1.27 mm Pitch)
pins: 1 TCK (in), 2 IN/CLK (in), 3 IN (in), 4 IN (in), 5 IN (in), 6 IN (in), 7 IN (in), 8 TMS (in), 9 IN (in), 10 IN (in), 11 IN (in), 12 IN (in), 13 IN (in), 14 GND (power), 15 TDI (in), 16 IN (in), 17 IO (io), 18 IO (io), 19 IO (io), 20 IO (io), 21 IO (io), 22 TDO (out), 23 IO (io), 24 IO (io), 25 IO (io), 26 IO (io), 27 IO (io), 28 VCC (power)

## ispGAL22V10AC-75LJ
designator U?
ispGAL22V10AC E²CMOS PLD Generic Array Logic: Low Power, 1.8 V, 7.5 ns, Commercial Grade
footprint PLCC28_N (Leaded Chip Carrier, 28-Leads, Body 11.5x11.5mm, Pitch 1.27mm, IPC Medium Density)
footprint PLCC28_L (Leaded Chip Carrier, 28-Leads, Body 11.5x11.5mm, Pitch 1.27mm, IPC High Density)
footprint PLCC28_M (Leaded Chip Carrier, 28-Leads, Body 11.5x11.5mm, Pitch 1.27mm, IPC Low Density)
3D model 22V10AC-PLCC28 (28-Pin Leaded Chip Carrier 1.27 mm Pitch)
pins: 1 TCK (in), 2 IN/CLK (in), 3 IN (in), 4 IN (in), 5 IN (in), 6 IN (in), 7 IN (in), 8 TMS (in), 9 IN (in), 10 IN (in), 11 IN (in), 12 IN (in), 13 IN (in), 14 GND (power), 15 TDI (in), 16 IN (in), 17 IO (io), 18 IO (io), 19 IO (io), 20 IO (io), 21 IO (io), 22 TDO (out), 23 IO (io), 24 IO (io), 25 IO (io), 26 IO (io), 27 IO (io), 28 VCC (power)

## ispGAL22V10AC-75LJI
designator U?
ispGAL22V10AC E²CMOS PLD Generic Array Logic: Low Power, 1.8 V, 7.5 ns, Industrial Grade
footprint PLCC28_N (Leaded Chip Carrier, 28-Leads, Body 11.5x11.5mm, Pitch 1.27mm, IPC Medium Density)
footprint PLCC28_L (Leaded Chip Carrier, 28-Leads, Body 11.5x11.5mm, Pitch 1.27mm, IPC High Density)
footprint PLCC28_M (Leaded Chip Carrier, 28-Leads, Body 11.5x11.5mm, Pitch 1.27mm, IPC Low Density)
3D model 22V10AC-PLCC28 (28-Pin Leaded Chip Carrier 1.27 mm Pitch)
pins: 1 TCK (in), 2 IN/CLK (in), 3 IN (in), 4 IN (in), 5 IN (in), 6 IN (in), 7 IN (in), 8 TMS (in), 9 IN (in), 10 IN (in), 11 IN (in), 12 IN (in), 13 IN (in), 14 GND (power), 15 TDI (in), 16 IN (in), 17 IO (io), 18 IO (io), 19 IO (io), 20 IO (io), 21 IO (io), 22 TDO (out), 23 IO (io), 24 IO (io), 25 IO (io), 26 IO (io), 27 IO (io), 28 VCC (power)

## ispGAL22V10AC-75LN
designator U?
ispGAL22V10AC E²CMOS PLD Generic Array Logic: Low Power, 1.8 V, 7.5 ns, Commercial Grade
footprint QFN32_N (QFN, 32-Leads, Body 5x5mm, Pitch 0.5mm, IPC Medium Density)
footprint QFN32_L (QFN, 32-Leads, Body 5x5mm, Pitch 0.5mm, IPC High Density)
footprint QFN32_M (QFN, 32-Leads, Body 5x5mm, Pitch 0.5mm, IPC Low Density)
pins: 1 IN (in), 2 IN (in), 3 IN (in), 4 TMS (in), 5 VCCO (power), 6 IN (in), 7 IN (in), 8 IN (in), 9 IN (in), 10 IN (in), 11 GND (power), 12 GNDO (power), 13 TDI (in), 14 IN (in), 15 IO (io), 16 IO (io), 17 IO (io), 18 IO (io), 19 IO (io), 20 GNDO (power), 21 TDO (out), 22 IO (io), 23 IO (io), 24 IO (io), 25 IO (io), 26 IO (io), 27 VCCO (power), 28 VCC (power), 29 TCK (in), 30 IN/CLK (in), 31 IN (in), 32 IN (in), 33 Thermal Pad (power)

## ispGAL22V10AC-75LNI
designator U?
ispGAL22V10AC E²CMOS PLD Generic Array Logic: Low Power, 1.8 V, 7.5 ns, Industrial Grade
footprint QFN32_N (QFN, 32-Leads, Body 5x5mm, Pitch 0.5mm, IPC Medium Density)
footprint QFN32_L (QFN, 32-Leads, Body 5x5mm, Pitch 0.5mm, IPC High Density)
footprint QFN32_M (QFN, 32-Leads, Body 5x5mm, Pitch 0.5mm, IPC Low Density)
pins: 1 IN (in), 2 IN (in), 3 IN (in), 4 TMS (in), 5 VCCO (power), 6 IN (in), 7 IN (in), 8 IN (in), 9 IN (in), 10 IN (in), 11 GND (power), 12 GNDO (power), 13 TDI (in), 14 IN (in), 15 IO (io), 16 IO (io), 17 IO (io), 18 IO (io), 19 IO (io), 20 GNDO (power), 21 TDO (out), 22 IO (io), 23 IO (io), 24 IO (io), 25 IO (io), 26 IO (io), 27 VCCO (power), 28 VCC (power), 29 TCK (in), 30 IN/CLK (in), 31 IN (in), 32 IN (in), 33 Thermal Pad (power)

## ispGAL22V10AV-5LJ
designator U?
ispGAL22V10AV E²CMOS PLD Generic Array Logic: Low Power, 3.3 V, 5.0 ns, Commercial Grade
footprint PLCC28_N (Leaded Chip Carrier, 28-Leads, Body 11.5x11.5mm, Pitch 1.27mm, IPC Medium Density)
footprint PLCC28_L (Leaded Chip Carrier, 28-Leads, Body 11.5x11.5mm, Pitch 1.27mm, IPC High Density)
footprint PLCC28_M (Leaded Chip Carrier, 28-Leads, Body 11.5x11.5mm, Pitch 1.27mm, IPC Low Density)
3D model 22V10AV-PLCC28 (28-Pin Leaded Chip Carrier 1.27 mm Pitch)
pins: 1 TCK (in), 2 IN/CLK (in), 3 IN (in), 4 IN (in), 5 IN (in), 6 IN (in), 7 IN (in), 8 TMS (in), 9 IN (in), 10 IN (in), 11 IN (in), 12 IN (in), 13 IN (in), 14 GND (power), 15 TDI (in), 16 IN (in), 17 IO (io), 18 IO (io), 19 IO (io), 20 IO (io), 21 IO (io), 22 TDO (out), 23 IO (io), 24 IO (io), 25 IO (io), 26 IO (io), 27 IO (io), 28 VCC (power)

## ispGAL22V10AV-5LJI
designator U?
ispGAL22V10AV E²CMOS PLD Generic Array Logic: Low Power, 3.3 V, 5.0 ns, Industrial Grade
footprint PLCC28_N (Leaded Chip Carrier, 28-Leads, Body 11.5x11.5mm, Pitch 1.27mm, IPC Medium Density)
footprint PLCC28_L (Leaded Chip Carrier, 28-Leads, Body 11.5x11.5mm, Pitch 1.27mm, IPC High Density)
footprint PLCC28_M (Leaded Chip Carrier, 28-Leads, Body 11.5x11.5mm, Pitch 1.27mm, IPC Low Density)
3D model 22V10AV-PLCC28 (28-Pin Leaded Chip Carrier 1.27 mm Pitch)
pins: 1 TCK (in), 2 IN/CLK (in), 3 IN (in), 4 IN (in), 5 IN (in), 6 IN (in), 7 IN (in), 8 TMS (in), 9 IN (in), 10 IN (in), 11 IN (in), 12 IN (in), 13 IN (in), 14 GND (power), 15 TDI (in), 16 IN (in), 17 IO (io), 18 IO (io), 19 IO (io), 20 IO (io), 21 IO (io), 22 TDO (out), 23 IO (io), 24 IO (io), 25 IO (io), 26 IO (io), 27 IO (io), 28 VCC (power)

## ispGAL22V10AV-5LN
designator U?
ispGAL22V10AV E²CMOS PLD Generic Array Logic: Low Power, 3.3 V, 5.0 ns, Commercial Grade
footprint QFN32_N (QFN, 32-Leads, Body 5x5mm, Pitch 0.5mm, IPC Medium Density)
footprint QFN32_L (QFN, 32-Leads, Body 5x5mm, Pitch 0.5mm, IPC High Density)
footprint QFN32_M (QFN, 32-Leads, Body 5x5mm, Pitch 0.5mm, IPC Low Density)
pins: 1 IN (in), 2 IN (in), 3 IN (in), 4 TMS (in), 5 VCCO (power), 6 IN (in), 7 IN (in), 8 IN (in), 9 IN (in), 10 IN (in), 11 GND (power), 12 GNDO (power), 13 TDI (in), 14 IN (in), 15 IO (io), 16 IO (io), 17 IO (io), 18 IO (io), 19 IO (io), 20 GNDO (power), 21 TDO (out), 22 IO (io), 23 IO (io), 24 IO (io), 25 IO (io), 26 IO (io), 27 VCCO (power), 28 VCC (power), 29 TCK (in), 30 IN/CLK (in), 31 IN (in), 32 IN (in), 33 Thermal Pad (power)

## ispGAL22V10AV-5LNI
designator U?
ispGAL22V10AV E²CMOS PLD Generic Array Logic: Low Power, 3.3 V, 5.0 ns, Industrial Grade
footprint QFN32_N (QFN, 32-Leads, Body 5x5mm, Pitch 0.5mm, IPC Medium Density)
footprint QFN32_L (QFN, 32-Leads, Body 5x5mm, Pitch 0.5mm, IPC High Density)
footprint QFN32_M (QFN, 32-Leads, Body 5x5mm, Pitch 0.5mm, IPC Low Density)
pins: 1 IN (in), 2 IN (in), 3 IN (in), 4 TMS (in), 5 VCCO (power), 6 IN (in), 7 IN (in), 8 IN (in), 9 IN (in), 10 IN (in), 11 GND (power), 12 GNDO (power), 13 TDI (in), 14 IN (in), 15 IO (io), 16 IO (io), 17 IO (io), 18 IO (io), 19 IO (io), 20 GNDO (power), 21 TDO (out), 22 IO (io), 23 IO (io), 24 IO (io), 25 IO (io), 26 IO (io), 27 VCCO (power), 28 VCC (power), 29 TCK (in), 30 IN/CLK (in), 31 IN (in), 32 IN (in), 33 Thermal Pad (power)

## ispGAL22V10AV-23LN
designator U?
ispGAL22V10AV E²CMOS PLD Generic Array Logic: Low Power, 3.3 V, 2.3 ns, Commercial Grade
footprint QFN32_N (QFN, 32-Leads, Body 5x5mm, Pitch 0.5mm, IPC Medium Density)
footprint QFN32_L (QFN, 32-Leads, Body 5x5mm, Pitch 0.5mm, IPC High Density)
footprint QFN32_M (QFN, 32-Leads, Body 5x5mm, Pitch 0.5mm, IPC Low Density)
pins: 1 IN (in), 2 IN (in), 3 IN (in), 4 TMS (in), 5 VCCO (power), 6 IN (in), 7 IN (in), 8 IN (in), 9 IN (in), 10 IN (in), 11 GND (power), 12 GNDO (power), 13 TDI (in), 14 IN (in), 15 IO (io), 16 IO (io), 17 IO (io), 18 IO (io), 19 IO (io), 20 GNDO (power), 21 TDO (out), 22 IO (io), 23 IO (io), 24 IO (io), 25 IO (io), 26 IO (io), 27 VCCO (power), 28 VCC (power), 29 TCK (in), 30 IN/CLK (in), 31 IN (in), 32 IN (in), 33 Thermal Pad (power)

## ispGAL22V10AV-28LJ
designator U?
ispGAL22V10AV E²CMOS PLD Generic Array Logic: Low Power, 3.3 V, 2.8 ns, Commercial Grade
footprint PLCC28_N (Leaded Chip Carrier, 28-Leads, Body 11.5x11.5mm, Pitch 1.27mm, IPC Medium Density)
footprint PLCC28_L (Leaded Chip Carrier, 28-Leads, Body 11.5x11.5mm, Pitch 1.27mm, IPC High Density)
footprint PLCC28_M (Leaded Chip Carrier, 28-Leads, Body 11.5x11.5mm, Pitch 1.27mm, IPC Low Density)
3D model 22V10AV-PLCC28 (28-Pin Leaded Chip Carrier 1.27 mm Pitch)
pins: 1 TCK (in), 2 IN/CLK (in), 3 IN (in), 4 IN (in), 5 IN (in), 6 IN (in), 7 IN (in), 8 TMS (in), 9 IN (in), 10 IN (in), 11 IN (in), 12 IN (in), 13 IN (in), 14 GND (power), 15 TDI (in), 16 IN (in), 17 IO (io), 18 IO (io), 19 IO (io), 20 IO (io), 21 IO (io), 22 TDO (out), 23 IO (io), 24 IO (io), 25 IO (io), 26 IO (io), 27 IO (io), 28 VCC (power)

## ispGAL22V10AV-75LJ
designator U?
ispGAL22V10AV E²CMOS PLD Generic Array Logic: Low Power, 3.3 V, 7.5 ns, Commercial Grade
footprint PLCC28_N (Leaded Chip Carrier, 28-Leads, Body 11.5x11.5mm, Pitch 1.27mm, IPC Medium Density)
footprint PLCC28_L (Leaded Chip Carrier, 28-Leads, Body 11.5x11.5mm, Pitch 1.27mm, IPC High Density)
footprint PLCC28_M (Leaded Chip Carrier, 28-Leads, Body 11.5x11.5mm, Pitch 1.27mm, IPC Low Density)
3D model 22V10AV-PLCC28 (28-Pin Leaded Chip Carrier 1.27 mm Pitch)
pins: 1 TCK (in), 2 IN/CLK (in), 3 IN (in), 4 IN (in), 5 IN (in), 6 IN (in), 7 IN (in), 8 TMS (in), 9 IN (in), 10 IN (in), 11 IN (in), 12 IN (in), 13 IN (in), 14 GND (power), 15 TDI (in), 16 IN (in), 17 IO (io), 18 IO (io), 19 IO (io), 20 IO (io), 21 IO (io), 22 TDO (out), 23 IO (io), 24 IO (io), 25 IO (io), 26 IO (io), 27 IO (io), 28 VCC (power)

## ispGAL22V10AV-75LJI
designator U?
ispGAL22V10AV E²CMOS PLD Generic Array Logic: Low Power, 3.3 V, 7.5 ns, Industrial Grade
footprint PLCC28_N (Leaded Chip Carrier, 28-Leads, Body 11.5x11.5mm, Pitch 1.27mm, IPC Medium Density)
footprint PLCC28_L (Leaded Chip Carrier, 28-Leads, Body 11.5x11.5mm, Pitch 1.27mm, IPC High Density)
footprint PLCC28_M (Leaded Chip Carrier, 28-Leads, Body 11.5x11.5mm, Pitch 1.27mm, IPC Low Density)
3D model 22V10AV-PLCC28 (28-Pin Leaded Chip Carrier 1.27 mm Pitch)
pins: 1 TCK (in), 2 IN/CLK (in), 3 IN (in), 4 IN (in), 5 IN (in), 6 IN (in), 7 IN (in), 8 TMS (in), 9 IN (in), 10 IN (in), 11 IN (in), 12 IN (in), 13 IN (in), 14 GND (power), 15 TDI (in), 16 IN (in), 17 IO (io), 18 IO (io), 19 IO (io), 20 IO (io), 21 IO (io), 22 TDO (out), 23 IO (io), 24 IO (io), 25 IO (io), 26 IO (io), 27 IO (io), 28 VCC (power)

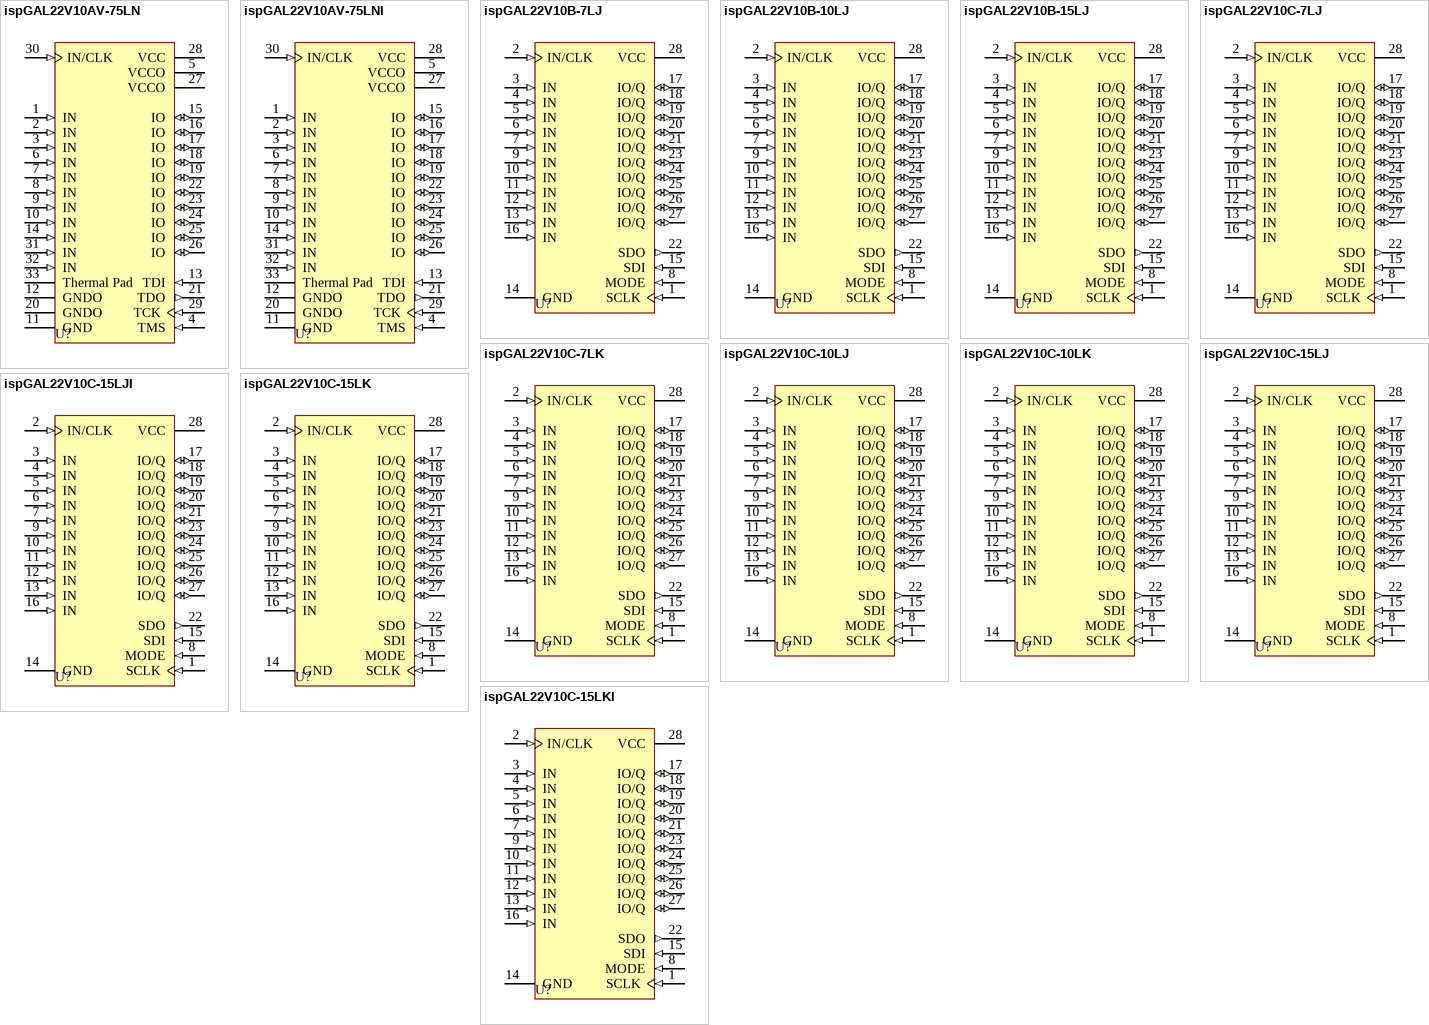
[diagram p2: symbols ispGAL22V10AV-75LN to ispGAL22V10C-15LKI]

## ispGAL22V10AV-75LN
designator U?
ispGAL22V10AV E²CMOS PLD Generic Array Logic: Low Power, 3.3 V, 7.5 ns, Commercial Grade
footprint QFN32_N (QFN, 32-Leads, Body 5x5mm, Pitch 0.5mm, IPC Medium Density)
footprint QFN32_L (QFN, 32-Leads, Body 5x5mm, Pitch 0.5mm, IPC High Density)
footprint QFN32_M (QFN, 32-Leads, Body 5x5mm, Pitch 0.5mm, IPC Low Density)
pins: 1 IN (in), 2 IN (in), 3 IN (in), 4 TMS (in), 5 VCCO (power), 6 IN (in), 7 IN (in), 8 IN (in), 9 IN (in), 10 IN (in), 11 GND (power), 12 GNDO (power), 13 TDI (in), 14 IN (in), 15 IO (io), 16 IO (io), 17 IO (io), 18 IO (io), 19 IO (io), 20 GNDO (power), 21 TDO (out), 22 IO (io), 23 IO (io), 24 IO (io), 25 IO (io), 26 IO (io), 27 VCCO (power), 28 VCC (power), 29 TCK (in), 30 IN/CLK (in), 31 IN (in), 32 IN (in), 33 Thermal Pad (power)

## ispGAL22V10AV-75LNI
designator U?
ispGAL22V10AV E²CMOS PLD Generic Array Logic: Low Power, 3.3 V, 7.5 ns, Industrial Grade
footprint QFN32_N (QFN, 32-Leads, Body 5x5mm, Pitch 0.5mm, IPC Medium Density)
footprint QFN32_L (QFN, 32-Leads, Body 5x5mm, Pitch 0.5mm, IPC High Density)
footprint QFN32_M (QFN, 32-Leads, Body 5x5mm, Pitch 0.5mm, IPC Low Density)
pins: 1 IN (in), 2 IN (in), 3 IN (in), 4 TMS (in), 5 VCCO (power), 6 IN (in), 7 IN (in), 8 IN (in), 9 IN (in), 10 IN (in), 11 GND (power), 12 GNDO (power), 13 TDI (in), 14 IN (in), 15 IO (io), 16 IO (io), 17 IO (io), 18 IO (io), 19 IO (io), 20 GNDO (power), 21 TDO (out), 22 IO (io), 23 IO (io), 24 IO (io), 25 IO (io), 26 IO (io), 27 VCCO (power), 28 VCC (power), 29 TCK (in), 30 IN/CLK (in), 31 IN (in), 32 IN (in), 33 Thermal Pad (power)

## ispGAL22V10B-7LJ
designator U?
ispGAL22V10 E²CMOS PLD Generic Array Logic: Low Power, 5.0 V, 7.5 ns, Commercial Grade
footprint PLCC28_N (Leaded Chip Carrier, 28-Leads, Body 11.5x11.5mm, Pitch 1.27mm, IPC Medium Density)
footprint PLCC28_L (Leaded Chip Carrier, 28-Leads, Body 11.5x11.5mm, Pitch 1.27mm, IPC High Density)
footprint PLCC28_M (Leaded Chip Carrier, 28-Leads, Body 11.5x11.5mm, Pitch 1.27mm, IPC Low Density)
3D model 22V10-PLCC28 (28-Pin Leaded Chip Carrier 1.27 mm Pitch)
pins: 1 SCLK (in), 2 IN/CLK (in), 3 IN (in), 4 IN (in), 5 IN (in), 6 IN (in), 7 IN (in), 8 MODE (in), 9 IN (in), 10 IN (in), 11 IN (in), 12 IN (in), 13 IN (in), 14 GND (power), 15 SDI (in), 16 IN (in), 17 IO/Q (io), 18 IO/Q (io), 19 IO/Q (io), 20 IO/Q (io), 21 IO/Q (io), 22 SDO (out), 23 IO/Q (io), 24 IO/Q (io), 25 IO/Q (io), 26 IO/Q (io), 27 IO/Q (io), 28 VCC (power)

## ispGAL22V10B-10LJ
designator U?
ispGAL22V10 E²CMOS PLD Generic Array Logic: Low Power, 5.0 V, 10 ns, Commercial Grade
footprint PLCC28_N (Leaded Chip Carrier, 28-Leads, Body 11.5x11.5mm, Pitch 1.27mm, IPC Medium Density)
footprint PLCC28_L (Leaded Chip Carrier, 28-Leads, Body 11.5x11.5mm, Pitch 1.27mm, IPC High Density)
footprint PLCC28_M (Leaded Chip Carrier, 28-Leads, Body 11.5x11.5mm, Pitch 1.27mm, IPC Low Density)
3D model 22V10-PLCC28 (28-Pin Leaded Chip Carrier 1.27 mm Pitch)
pins: 1 SCLK (in), 2 IN/CLK (in), 3 IN (in), 4 IN (in), 5 IN (in), 6 IN (in), 7 IN (in), 8 MODE (in), 9 IN (in), 10 IN (in), 11 IN (in), 12 IN (in), 13 IN (in), 14 GND (power), 15 SDI (in), 16 IN (in), 17 IO/Q (io), 18 IO/Q (io), 19 IO/Q (io), 20 IO/Q (io), 21 IO/Q (io), 22 SDO (out), 23 IO/Q (io), 24 IO/Q (io), 25 IO/Q (io), 26 IO/Q (io), 27 IO/Q (io), 28 VCC (power)

## ispGAL22V10B-15LJ
designator U?
ispGAL22V10 E²CMOS PLD Generic Array Logic: Low Power, 5.0 V, 15 ns, Commercial Grade
footprint PLCC28_N (Leaded Chip Carrier, 28-Leads, Body 11.5x11.5mm, Pitch 1.27mm, IPC Medium Density)
footprint PLCC28_L (Leaded Chip Carrier, 28-Leads, Body 11.5x11.5mm, Pitch 1.27mm, IPC High Density)
footprint PLCC28_M (Leaded Chip Carrier, 28-Leads, Body 11.5x11.5mm, Pitch 1.27mm, IPC Low Density)
3D model 22V10-PLCC28 (28-Pin Leaded Chip Carrier 1.27 mm Pitch)
pins: 1 SCLK (in), 2 IN/CLK (in), 3 IN (in), 4 IN (in), 5 IN (in), 6 IN (in), 7 IN (in), 8 MODE (in), 9 IN (in), 10 IN (in), 11 IN (in), 12 IN (in), 13 IN (in), 14 GND (power), 15 SDI (in), 16 IN (in), 17 IO/Q (io), 18 IO/Q (io), 19 IO/Q (io), 20 IO/Q (io), 21 IO/Q (io), 22 SDO (out), 23 IO/Q (io), 24 IO/Q (io), 25 IO/Q (io), 26 IO/Q (io), 27 IO/Q (io), 28 VCC (power)

## ispGAL22V10C-7LJ
designator U?
ispGAL22V10 E²CMOS PLD Generic Array Logic: Low Power, 5.0 V, 7.5 ns, Commercial Grade
footprint PLCC28_N (Leaded Chip Carrier, 28-Leads, Body 11.5x11.5mm, Pitch 1.27mm, IPC Medium Density)
footprint PLCC28_L (Leaded Chip Carrier, 28-Leads, Body 11.5x11.5mm, Pitch 1.27mm, IPC High Density)
footprint PLCC28_M (Leaded Chip Carrier, 28-Leads, Body 11.5x11.5mm, Pitch 1.27mm, IPC Low Density)
3D model 22V10-PLCC28 (28-Pin Leaded Chip Carrier 1.27 mm Pitch)
pins: 1 SCLK (in), 2 IN/CLK (in), 3 IN (in), 4 IN (in), 5 IN (in), 6 IN (in), 7 IN (in), 8 MODE (in), 9 IN (in), 10 IN (in), 11 IN (in), 12 IN (in), 13 IN (in), 14 GND (power), 15 SDI (in), 16 IN (in), 17 IO/Q (io), 18 IO/Q (io), 19 IO/Q (io), 20 IO/Q (io), 21 IO/Q (io), 22 SDO (out), 23 IO/Q (io), 24 IO/Q (io), 25 IO/Q (io), 26 IO/Q (io), 27 IO/Q (io), 28 VCC (power)

## ispGAL22V10C-7LK
designator U?
ispGAL22V10 E²CMOS PLD Generic Array Logic: Low Power, 5.0 V, 7.5 ns, Commercial Grade
footprint SSOP28 (SSOP; 28 Leads; Body Width 5.3 mm; Pitch 0.65 mm)
3D model SSOP28 (SSOP; 28 Leads; Body Width 5.3 mm; Pitch 0.65 mm)
pins: 1 SCLK (in), 2 IN/CLK (in), 3 IN (in), 4 IN (in), 5 IN (in), 6 IN (in), 7 IN (in), 8 MODE (in), 9 IN (in), 10 IN (in), 11 IN (in), 12 IN (in), 13 IN (in), 14 GND (power), 15 SDI (in), 16 IN (in), 17 IO/Q (io), 18 IO/Q (io), 19 IO/Q (io), 20 IO/Q (io), 21 IO/Q (io), 22 SDO (out), 23 IO/Q (io), 24 IO/Q (io), 25 IO/Q (io), 26 IO/Q (io), 27 IO/Q (io), 28 VCC (power)

## ispGAL22V10C-10LJ
designator U?
ispGAL22V10 E²CMOS PLD Generic Array Logic: Low Power, 5.0 V, 10 ns, Commercial Grade
footprint PLCC28_N (Leaded Chip Carrier, 28-Leads, Body 11.5x11.5mm, Pitch 1.27mm, IPC Medium Density)
footprint PLCC28_L (Leaded Chip Carrier, 28-Leads, Body 11.5x11.5mm, Pitch 1.27mm, IPC High Density)
footprint PLCC28_M (Leaded Chip Carrier, 28-Leads, Body 11.5x11.5mm, Pitch 1.27mm, IPC Low Density)
3D model 22V10-PLCC28 (28-Pin Leaded Chip Carrier 1.27 mm Pitch)
pins: 1 SCLK (in), 2 IN/CLK (in), 3 IN (in), 4 IN (in), 5 IN (in), 6 IN (in), 7 IN (in), 8 MODE (in), 9 IN (in), 10 IN (in), 11 IN (in), 12 IN (in), 13 IN (in), 14 GND (power), 15 SDI (in), 16 IN (in), 17 IO/Q (io), 18 IO/Q (io), 19 IO/Q (io), 20 IO/Q (io), 21 IO/Q (io), 22 SDO (out), 23 IO/Q (io), 24 IO/Q (io), 25 IO/Q (io), 26 IO/Q (io), 27 IO/Q (io), 28 VCC (power)

## ispGAL22V10C-10LK
designator U?
ispGAL22V10 E²CMOS PLD Generic Array Logic: Low Power, 5.0 V, 10 ns, Commercial Grade
footprint SSOP28 (SSOP; 28 Leads; Body Width 5.3 mm; Pitch 0.65 mm)
3D model SSOP28 (SSOP; 28 Leads; Body Width 5.3 mm; Pitch 0.65 mm)
pins: 1 SCLK (in), 2 IN/CLK (in), 3 IN (in), 4 IN (in), 5 IN (in), 6 IN (in), 7 IN (in), 8 MODE (in), 9 IN (in), 10 IN (in), 11 IN (in), 12 IN (in), 13 IN (in), 14 GND (power), 15 SDI (in), 16 IN (in), 17 IO/Q (io), 18 IO/Q (io), 19 IO/Q (io), 20 IO/Q (io), 21 IO/Q (io), 22 SDO (out), 23 IO/Q (io), 24 IO/Q (io), 25 IO/Q (io), 26 IO/Q (io), 27 IO/Q (io), 28 VCC (power)

## ispGAL22V10C-15LJ
designator U?
ispGAL22V10 E²CMOS PLD Generic Array Logic: Low Power, 5.0 V, 15 ns, Commercial Grade
footprint PLCC28_N (Leaded Chip Carrier, 28-Leads, Body 11.5x11.5mm, Pitch 1.27mm, IPC Medium Density)
footprint PLCC28_L (Leaded Chip Carrier, 28-Leads, Body 11.5x11.5mm, Pitch 1.27mm, IPC High Density)
footprint PLCC28_M (Leaded Chip Carrier, 28-Leads, Body 11.5x11.5mm, Pitch 1.27mm, IPC Low Density)
3D model 22V10-PLCC28 (28-Pin Leaded Chip Carrier 1.27 mm Pitch)
pins: 1 SCLK (in), 2 IN/CLK (in), 3 IN (in), 4 IN (in), 5 IN (in), 6 IN (in), 7 IN (in), 8 MODE (in), 9 IN (in), 10 IN (in), 11 IN (in), 12 IN (in), 13 IN (in), 14 GND (power), 15 SDI (in), 16 IN (in), 17 IO/Q (io), 18 IO/Q (io), 19 IO/Q (io), 20 IO/Q (io), 21 IO/Q (io), 22 SDO (out), 23 IO/Q (io), 24 IO/Q (io), 25 IO/Q (io), 26 IO/Q (io), 27 IO/Q (io), 28 VCC (power)

## ispGAL22V10C-15LJI
designator U?
ispGAL22V10 E²CMOS PLD Generic Array Logic: Low Power, 5.0 V, 15 ns, Industrial Grade
footprint PLCC28_N (Leaded Chip Carrier, 28-Leads, Body 11.5x11.5mm, Pitch 1.27mm, IPC Medium Density)
footprint PLCC28_L (Leaded Chip Carrier, 28-Leads, Body 11.5x11.5mm, Pitch 1.27mm, IPC High Density)
footprint PLCC28_M (Leaded Chip Carrier, 28-Leads, Body 11.5x11.5mm, Pitch 1.27mm, IPC Low Density)
3D model 22V10-PLCC28 (28-Pin Leaded Chip Carrier 1.27 mm Pitch)
pins: 1 SCLK (in), 2 IN/CLK (in), 3 IN (in), 4 IN (in), 5 IN (in), 6 IN (in), 7 IN (in), 8 MODE (in), 9 IN (in), 10 IN (in), 11 IN (in), 12 IN (in), 13 IN (in), 14 GND (power), 15 SDI (in), 16 IN (in), 17 IO/Q (io), 18 IO/Q (io), 19 IO/Q (io), 20 IO/Q (io), 21 IO/Q (io), 22 SDO (out), 23 IO/Q (io), 24 IO/Q (io), 25 IO/Q (io), 26 IO/Q (io), 27 IO/Q (io), 28 VCC (power)

## ispGAL22V10C-15LK
designator U?
ispGAL22V10 E²CMOS PLD Generic Array Logic: Low Power, 5.0 V, 15 ns, Commercial Grade
footprint SSOP28 (SSOP; 28 Leads; Body Width 5.3 mm; Pitch 0.65 mm)
3D model SSOP28 (SSOP; 28 Leads; Body Width 5.3 mm; Pitch 0.65 mm)
pins: 1 SCLK (in), 2 IN/CLK (in), 3 IN (in), 4 IN (in), 5 IN (in), 6 IN (in), 7 IN (in), 8 MODE (in), 9 IN (in), 10 IN (in), 11 IN (in), 12 IN (in), 13 IN (in), 14 GND (power), 15 SDI (in), 16 IN (in), 17 IO/Q (io), 18 IO/Q (io), 19 IO/Q (io), 20 IO/Q (io), 21 IO/Q (io), 22 SDO (out), 23 IO/Q (io), 24 IO/Q (io), 25 IO/Q (io), 26 IO/Q (io), 27 IO/Q (io), 28 VCC (power)

## ispGAL22V10C-15LKI
designator U?
ispGAL22V10 E²CMOS PLD Generic Array Logic: Low Power, 5.0 V, 15 ns, Industrial Grade
footprint SSOP28 (SSOP; 28 Leads; Body Width 5.3 mm; Pitch 0.65 mm)
3D model SSOP28 (SSOP; 28 Leads; Body Width 5.3 mm; Pitch 0.65 mm)
pins: 1 SCLK (in), 2 IN/CLK (in), 3 IN (in), 4 IN (in), 5 IN (in), 6 IN (in), 7 IN (in), 8 MODE (in), 9 IN (in), 10 IN (in), 11 IN (in), 12 IN (in), 13 IN (in), 14 GND (power), 15 SDI (in), 16 IN (in), 17 IO/Q (io), 18 IO/Q (io), 19 IO/Q (io), 20 IO/Q (io), 21 IO/Q (io), 22 SDO (out), 23 IO/Q (io), 24 IO/Q (io), 25 IO/Q (io), 26 IO/Q (io), 27 IO/Q (io), 28 VCC (power)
